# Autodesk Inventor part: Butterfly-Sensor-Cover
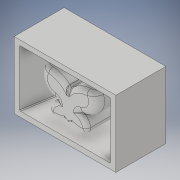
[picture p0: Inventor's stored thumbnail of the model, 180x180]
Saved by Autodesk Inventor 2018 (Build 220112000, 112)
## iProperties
Created: 2018-03
Part Number: Butterfly-Sensor-Cover
Material: Generic
Document SubType Name: Modeling
Designer: katin
Density: 1 g/cm^3
Appearance: Default
Author: katin
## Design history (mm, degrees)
sketch "Sketch2"
  geometry: L1 (0, 0)-(0, 15.875); A1 r 5.613 centre (-4.107, 12.049) between (0.776, 14.817) and (0, 15.875); A2 r 8.265 centre (6.02, 14.227) between (6.773, 5.997) and (13.223, 18.28); A3 r 7.847 centre (1.827, -0.095) between (9.673, -0.23) and (6.773, 5.997); A4 r 11.212 centre (6.154, 10.416) between (0.951, 0.484) and (9.673, -0.23); A5 r 30.522 centre (-13.365, 27.44) between (0, 0) and (0.951, 0.484); A6 r 13.681 centre (10.232, 4.93) between (13.223, 18.28) and (0.776, 14.817)
  constraints: 12 point on circle, 6 centre point, 2 end point
  dimensions: "d2" = 15.875 distance of L1.start L1.end
extrude "Extrusion1" new body sketch "Sketch2" distance "d0" = 21.5; taper "d1" = 0 deg
fillet "Fillet1" dims "d3" = 4
fillet "Fillet2" dims "d4" = 2
fillet "Fillet3" dims "d5" = 2
fillet "Fillet4" dims "d6" = 2
fillet "Fillet5" dims "d7" = 1
fillet "Fillet6" dims "d8" = 1
fillet "Fillet7" dims "d9" = 0.32
fillet "Fillet8" dims "d10" = 0.32
fillet "Fillet9" dims "d11" = 0.32
mirror "Mirror1"
sketch "Sketch4"
  geometry: L1 (-22.894, 23.1)-(22.946, 23.1); L2 (22.946, 23.1)-(22.946, -5.432); L3 (22.946, -5.432)-(-22.894, -5.432); L4 (-22.894, -5.432)-(-22.894, 23.1); 1 further point
  constraints: 8 end point, 2 parallel, 1 horizontal, 1 perpendicular
extrude "Extrusion3" join sketch "Sketch4" distance "d20" = 2; taper "d21" = 0 deg
sketch "Sketch5"
  geometry: L1 (-25.4, 25.4)-(25.4, 25.4); L2 (25.4, 25.4)-(25.4, -7.938); L3 (25.4, -7.938)-(-25.4, -7.938); L4 (-25.4, -7.938)-(-25.4, 25.4); L5 (-22.618, 22.976)-(22.659, 22.976); L6 (22.659, 22.976)-(22.659, -5.278); L7 (22.659, -5.278)-(-22.618, -5.278); L8 (-22.618, -5.278)-(-22.618, 22.976); 3 further points
  constraints: 16 end point, 4 parallel, 2 horizontal, 2 perpendicular
extrude "Extrusion4" join sketch "Sketch5" distance "d22" = 23; taper "d23" = 0 deg; dims "d36" = 2, "d37" = 0
sketch "Sketch6"
  geometry: L1 (13.723, 17.221)-(23.812, 19.05); L2 (23.812, 19.05)-(24.704, 14.13); L3 (24.704, 14.13)-(14.031, 12.196); L4 (14.031, 12.196)-(13.723, 17.221); A1 r 13.681 centre (10.232, 4.93) between (12.138, 18.477) and (1.059, 15.08) reference; A2 r 8.265 centre (6.02, 14.227) between (7.453, 6.088) and (13.723, 17.221) reference; 2 further points
  constraints: 8 end point, 2 point on circle, 1 perpendicular
  dimensions: "d53" = 5 distance of L1.end L2.end; "d54" = 90 deg angle of L2 L3
chamfer "Chamfer1" distance "d38" = 4; stored, may be unused: second distance "d39" = 23, angle "d40" = 5 deg
chamfer "Chamfer2" distance "d41" = 4; stored, may be unused: second distance "d42" = 23, angle "d43" = 5 deg
chamfer "Chamfer3" distance "d44" = 0.1; stored, may be unused: second distance "d45" = 23, angle "d46" = 5 deg
chamfer "Chamfer4" distance "d47" = 0.1; stored, may be unused: second distance "d48" = 23, angle "d49" = 5 deg
fillet "Fillet16" dims "d51" = 0.2
fillet "Fillet17" dims "d52" = 0.4
extrude "Extrusion6" join sketch "Sketch6" distance "d55" = 2; taper "d56" = 0 deg
fillet "Fillet18" dims "d57" = 0.4
body "Solid1"
